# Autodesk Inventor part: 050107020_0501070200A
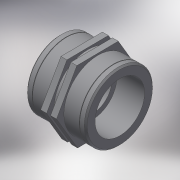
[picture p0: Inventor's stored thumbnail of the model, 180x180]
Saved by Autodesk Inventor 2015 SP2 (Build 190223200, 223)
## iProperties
Created: 2017-05
Part Number: 050107020_0501070200A
Material: Generic
Description: PLASSON SOCKET PP 2"-2"
Document SubType Name: Modeling
Designer: KIM
Density: 1 g/cm^3
Appearance: Default
Author: KIM
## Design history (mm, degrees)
derived "050107.ipt"
feature "Solid1::050107.ipt"
tag "TaggingFeature1"
body "Solid1"
other parameters: "d0" = 66, "d2" = 56.656, "d3" = 31, "d5" = 75, "d6" = 71.25, "d7" = 45.3248, "d14" = 0, "d15" = 1.69968, "d18" = 6.6, "d19" = 2.2, "d20" = 0.5, "d21" = 0.5, "d22" = 71.25, "Rp_" = 56.656, "H_" = 66, "l_2" = 31, "E_" = 75
